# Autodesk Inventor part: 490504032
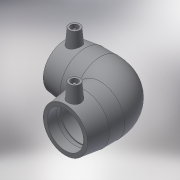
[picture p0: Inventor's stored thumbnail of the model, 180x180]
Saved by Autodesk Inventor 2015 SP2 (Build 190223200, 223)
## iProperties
Created: 2017-06
Part Number: 490504032
Material: Generic
Description: PLASSON 90° ELBOW 32
Document SubType Name: Modeling
Designer: KIM
Mass: 55.0731 g
Surface Area: 148.067 cm^2
Volume: 55.0731 cm^3
Density: 1 g/cm^3
Appearance: Default
Author: KIM
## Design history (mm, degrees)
derived "490504.ipt"
feature "Solid1::490504.ipt"
tag "TaggingFeature1"
body "Solid1"
other parameters: "d2" = 44, "d4" = 24.41176, "d5" = 39.6, "d8" = 168 deg, "d10" = 16, "d11" = 5.33333, "d14" = 17.6296, "d18" = 32, "d19" = 3.52592, "d20" = 168 deg, "d22" = 40.48, "d23" = 44, "d24" = 39.2656, "d29" = 43, "d30" = 15, "d31" = 49.8, "d34" = 5 deg, "d35" = 15, "d39" = 5 deg, "d41" = 4, "d42" = 14, "d43" = 0, "d45" = 4, "d46" = 14, "d47" = 0, "d49" = 32, "d50" = 27.2, "d51" = 16, "d54" = 90 deg, "d65" = 32, "d67" = 45 deg, "d71" = 90 deg, "d75" = 2.2, "d82" = 45 deg, "d84" = 39.6, "d86" = 19.8, "d87" = 90 deg, "d91" = 0, "d93" = 0, "d94" = 90 deg, "d95" = 20.24, "d98" = 83, "d101" = 3, "d102" = 0, "d103" = 3, "d104" = 0, "d105" = 11.6, "d106" = 2.9, "d107" = 83, "d110" = 22, "d_" = 32, "L_" = 83, "D_" = 44, "A_" = 43, "d_2" = 12
